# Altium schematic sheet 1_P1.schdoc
size 307 x 218 mm; Symbol: Drawing-Symbol_A4; Device: Drawing-Symbol_A4; @Project Name: MSDRV4; @Page Count: 1; @Update Date: 2025-03-06; @Create Date: 2025-01-27; @Schematic Name: Schematic1_1; @Page No: 1; @Page Name: P1; Company: EasyEDA.com; Version: V1.0; Page Size: A4; @Create Time: 16:14:18; @Update Time: 21:27:29; Width: 1170; Height: 825; Region Start: 1; X Region Count: 6; Y Region Count: 4; Blade Width: 10; Title Block Position: 3; @Board Name: Board1_1
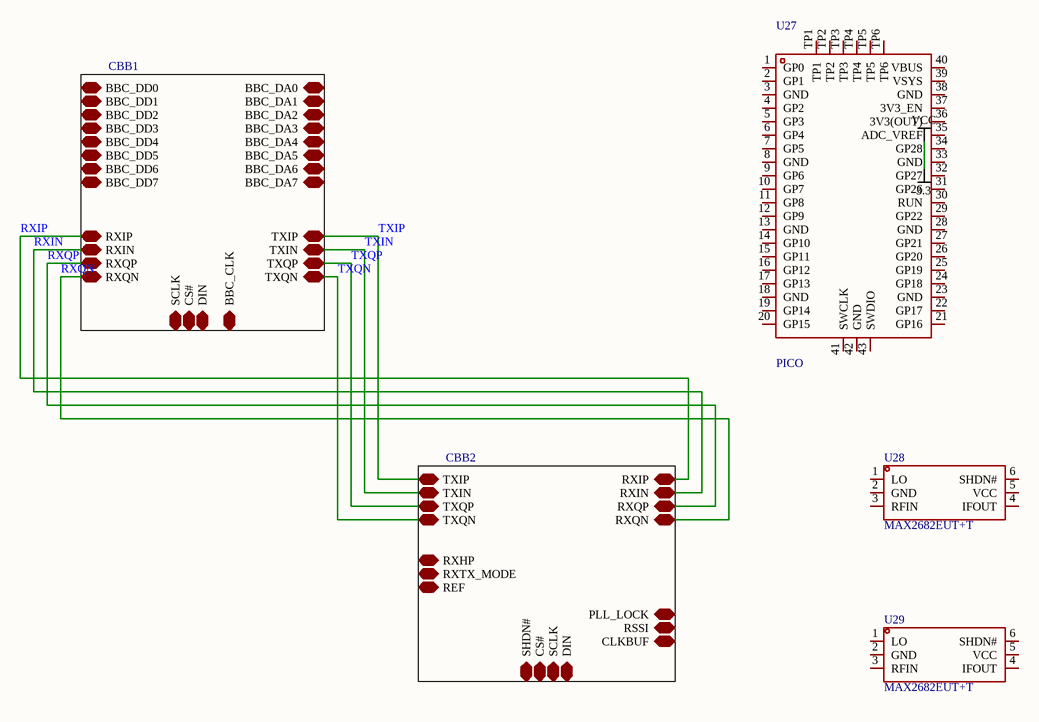
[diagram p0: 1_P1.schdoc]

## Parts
U27  PICO  [comm-smd_l51.0-w21.0-p2.54_sc0916]
U28  MAX2682EUT+T  [SOT-23-6_L2.9-W1.6-P0.95-LS2.8-TL]
U29  MAX2682EUT+T  [SOT-23-6_L2.9-W1.6-P0.95-LS2.8-TL]

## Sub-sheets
CBB1 = ?: BBC_DD0, BBC_DD1, BBC_DD2, BBC_DD3, BBC_DD4, BBC_DD5, BBC_DD6, BBC_DD7, SCLK, CS#, DIN, RXIP, RXIN, RXQP, RXQN, BBC_CLK, BBC_DA0, BBC_DA1, BBC_DA2, BBC_DA3, BBC_DA4, BBC_DA5, BBC_DA6, BBC_DA7, TXIP, TXIN, TXQP, TXQN  | Symbol: BBC_2024_REUSE; Device: BBC_2024_REUSE; Relevance: []
CBB2 = ?: SHDN#, CS#, SCLK, DIN, RSSI, RXTX_MODE, RXHP, TXIP, TXIN, TXQP, TXQN, PLL_LOCK, CLKBUF, RXIP, RXIN, RXQP, RXQN, REF  | Symbol: MAX2831_2024_REUSE; Device: MAX2831_2024_REUSE; Relevance: []

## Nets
RXIN: sheet CBB1/RXIN, sheet CBB2/RXIN
RXIP: sheet CBB1/RXIP, sheet CBB2/RXIP
RXQN: sheet CBB1/RXQN, sheet CBB2/RXQN
RXQP: sheet CBB1/RXQP, sheet CBB2/RXQP
TXIN: sheet CBB1/TXIN, sheet CBB2/TXIN
TXIP: sheet CBB1/TXIP, sheet CBB2/TXIP
TXQN: sheet CBB1/TXQN, sheet CBB2/TXQN
TXQP: sheet CBB1/TXQP, sheet CBB2/TXQP

Not connected (* = marked no-connect by the designer): U27 1(GP0) 2(GP1) 3(GND) 4(GP2) 5(GP3) 6(GP4) 7(GP5) 8(GND) 9(GP6) 10(GP7) 11(GP8) 12(GP9) 13(GND) 14(GP10) 15(GP11) 16(GP12) 17(GP13) 18(GND) 19(GP14) 20(GP15) 21(GP16) 22(GP17) 23(GND) 24(GP18) 25(GP19) 26(GP20) 27(GP21) 28(GND) 29(GP22) 30(RUN) 31(GP26) 32(GP27) 33(GND) 34(GP28) 35(ADC_VREF) 36(3V3(OUT)) 37(3V3_EN) 38(GND) 39(VSYS) 40(VBUS) 41(SWCLK) 42(GND) 43(SWDIO) TP1 TP2 TP3 TP4 TP5 TP6; U28 1(LO) 2(GND) 3(RFIN) 4(IFOUT) 5(VCC) 6(SHDN#); U29 1(LO) 2(GND) 3(RFIN) 4(IFOUT) 5(VCC) 6(SHDN#)

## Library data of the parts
U27 = PICO: Manufacturer: Raspberry Pi(树莓派); Add into BOM: yes
U28 U29 = MAX2682EUT+T: Manufacturer: ADI(亚德诺)/MAXIM(美信); Add into BOM: yes; Frequency Range: 400MHz~2500MHz; Gain/Loss: 14.7dB; Noise Figure: 6.5dB; Supply Voltage: 2.7V~5.5V; Supply Current: 15mA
